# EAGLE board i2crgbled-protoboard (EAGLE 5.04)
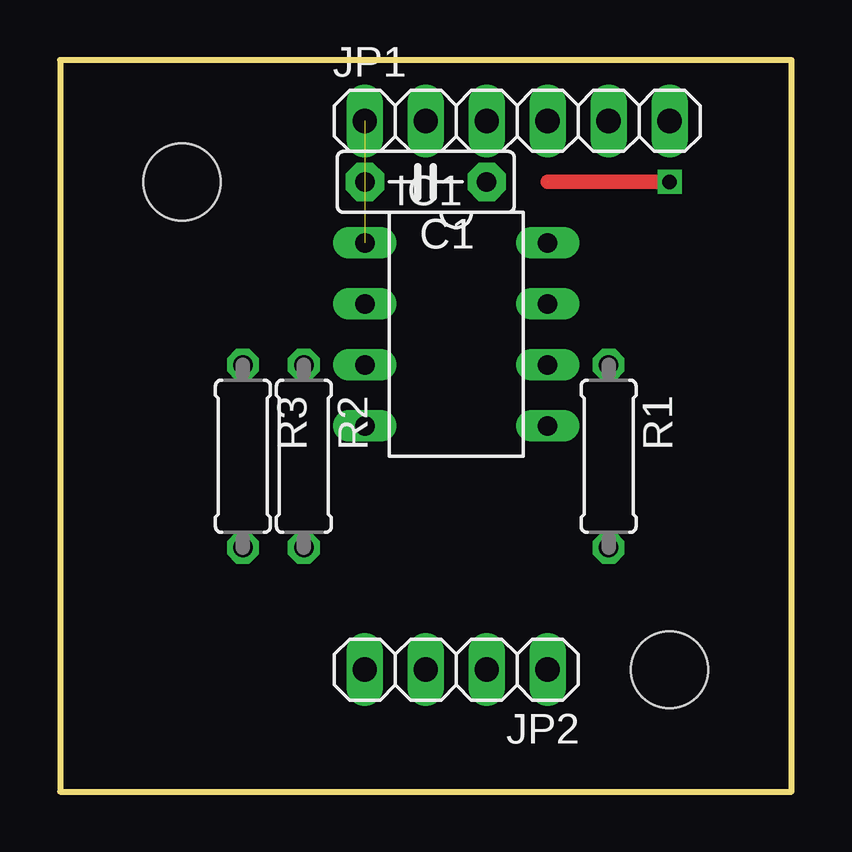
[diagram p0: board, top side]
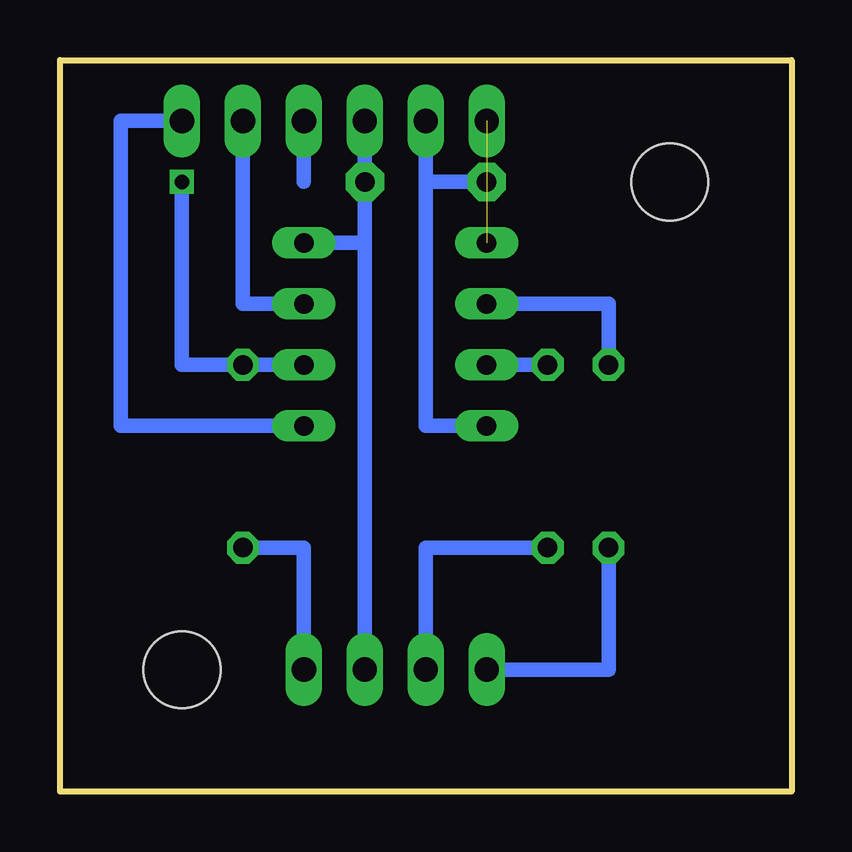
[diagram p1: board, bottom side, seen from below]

Size 30.48 x 30.48 mm. Coordinates in mm from the lower left corner, seen from the top.
Outline: 30.48,0 30.48,30.48 0,30.48 0,0 30.48,0
Copper layers (1*16): Top 0.035mm / dielectric 1.5mm / Bottom 0.035mm
Design rules "default": minimum track width 10mil, minimum drill 24mil, track to track 8mil, track to pad 8mil, pad to pad 8mil, via to via 8mil, smd to smd 8mil, copper to edge 40mil, drill to drill 8mil, minimum pad ring 10mil, minimum via ring 8mil, stop-mask expansion 4mil, vias tented up to drill 0mil, thermal gap 10mil
Holes 3.2 mm at 25.4,5.08 5.08,25.4

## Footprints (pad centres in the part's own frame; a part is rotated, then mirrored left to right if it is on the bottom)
C5B2.5 = drill 0.813 pad 1.6 octagon: 1 -2.54,0; 2 2.54,0
DIL08 = drill 0.813 long: 1 -3.81,-3.81; 2 -1.27,-3.81; 3 1.27,-3.81; 4 3.81,-3.81; 5 3.81,3.81; 6 1.27,3.81; 7 -1.27,3.81; 8 -3.81,3.81
1X06 = drill 1.016 long: 1 -6.35,0; 2 -3.81,0; 3 -1.27,0; 4 1.27,0; 5 3.81,0; 6 6.35,0
1X04 = drill 1.016 long: 1 -3.81,0; 2 -1.27,0; 3 1.27,0; 4 3.81,0
0207/7 = drill 0.813 octagon: 1 -3.81,0; 2 3.81,0

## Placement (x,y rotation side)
C1  [C5B2.5]  15.24,25.4 180 top
IC1  ATtiny45-20PU  [DIL08]  16.51,19.05 270 top
JP1  [1X06]  19.05,27.94 0 top
JP2  RGB_LED  [1X04]  16.51,5.08 180 top
R1  110R  [0207/7]  22.86,13.97 270 top
R2  110R  [0207/7]  10.16,13.97 270 top
R3  110R  [0207/7]  7.62,13.97 270 top

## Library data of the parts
C1 = capacitor-wima
IC1 = avr-5
JP1 JP2 = pinhead
R1-R3 = rcl

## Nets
GND: C1.2 IC1.4 JP1.2
N$1: IC1.1 JP1.1
N$2: IC1.3 R2.1
N$3: IC1.5 JP1.6
N$4: IC1.6 JP1.4 R1.1
N$5: IC1.7 JP1.5
N$6: IC1.2 R3.1
N$7: JP2.1 R1.2
N$8: JP2.3 R2.2
N$9: JP2.4 R3.2
VCC: C1.1 IC1.8 JP1.3 JP2.2

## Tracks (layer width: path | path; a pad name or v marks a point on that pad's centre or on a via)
GND
  Bottom 0.61: 15.24,25.4 15.24,15.24 IC1.4 | JP1.2 15.24,25.4 | 15.24,25.4 C1.2
N$1  (1 unrouted)
N$2
  Bottom 0.61: IC1.3 R2.1
N$3
  Bottom 0.61: IC1.5 27.94,15.24 27.94,27.94 JP1.6
N$4  (via drill 0.6)  (1 unrouted)
  Top 0.61: v25.4,25.4 20.32,25.4
  Bottom 0.61: R1.1 IC1.6 25.4,17.78 v25.4,25.4 | 20.32,25.4 JP1.4
N$5
  Bottom 0.61: IC1.7 22.86,20.32 JP1.5
N$6
  Bottom 0.61: IC1.2 7.62,20.32 R3.1
N$7
  Bottom 0.61: JP2.1 20.32,10.16 R1.2
N$8
  Bottom 0.61: R2.2 15.24,10.16 JP2.3
N$9
  Bottom 0.61: JP2.4 7.62,5.08 R3.2
VCC
  Bottom 0.61: JP1.3 C1.1 17.78,22.86 | IC1.8 17.78,22.86 | 17.78,22.86 JP2.2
